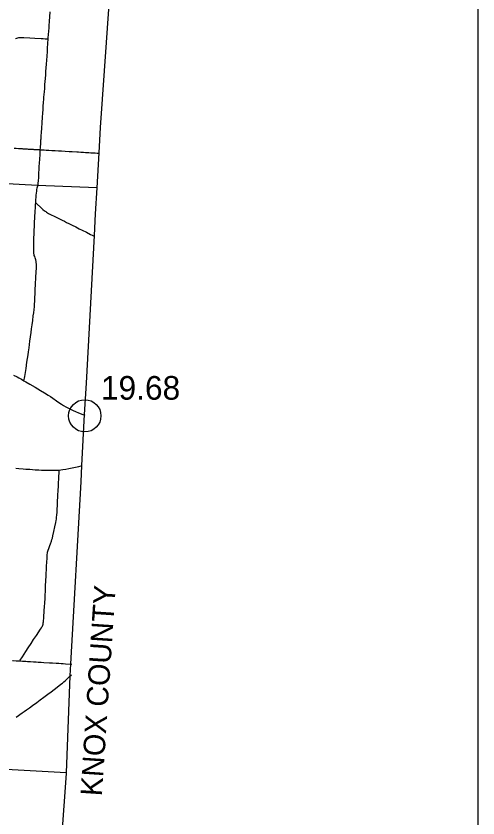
# Model space of a CAD drawing. Extents: x 1813937 to 1948437, y 826606 to 1022856.
# Drawn here: x 1926985 to 1948437, y 878544 to 915824 of the extents above; entities that cross this region are included whole.
import ezdxf

# ---------------------------------------------------------------- set-up
doc = ezdxf.new("R2010")
doc.units = 0
for name, color, linetype in [('Default', 7, 'Continuous'), ('GM_X_Adjacent_County_Text', 7, 'Continuous'), ('GM_X_County', 7, 'Continuous'), ('GM_X_County_Road', 7, 'Continuous'), ('GM_X_State_Route', 7, 'Continuous'), ('GM_X_Township', 7, 'Continuous'), ('GM_X_Township_Road', 7, 'Continuous'), ('SC_Scratch1', 7, 'Continuous')]:
    doc.layers.add(name, color=color, linetype=linetype)

msp = doc.modelspace()

# ---------------------------------------------------------------- linework, layer by layer
at = {"layer": 'Default'}
msp.add_circle((1930177, 897239), 750, dxfattribs=at)
at = {"layer": 'GM_X_County'}
msp.add_lwpolyline([(1931473, 919044), (1931168, 914595), (1930891, 910644), (1930824, 909461), (1930733, 907844), (1930665, 906634), (1930611, 905616), (1930247, 898751), (1930144, 897297), (1930019, 894924), (1929994, 894165), (1929509, 885709), (1929483, 885147), (1929313, 880637), (1929312, 880613), (1928987, 876105)], dxfattribs=at)
at = {"layer": 'GM_X_County_Road'}
for points in [[(1926898, 909680), (1926996, 909675), (1927094, 909669), (1927223, 909662), (1927270, 909659), (1927305, 909657), (1927346, 909654), (1927391, 909652), (1927420, 909650), (1927464, 909647), (1927502, 909645), (1927550, 909642), (1927602, 909639), (1927632, 909637), (1927662, 909636), (1927708, 909633), (1927749, 909630), (1927785, 909628), (1927815, 909626), (1927979, 909618), (1928077, 909613), (1928111, 909611)], [(1928111, 909611), (1928158, 909609), (1928289, 909601), (1928387, 909594), (1928502, 909587), (1928649, 909580), (1928714, 909577), (1928796, 909572), (1928960, 909561), (1929091, 909553), (1929270, 909541), (1929447, 909531), (1929512, 909527), (1929594, 909522), (1929806, 909511), (1929887, 909506), (1929986, 909499), (1930116, 909490), (1930214, 909485), (1930361, 909477), (1930459, 909472), (1930590, 909465), (1930655, 909461), (1930754, 909453), (1930800, 909450), (1930838, 909448)], [(1926968, 894804), (1927115, 894792), (1927311, 894776), (1927442, 894766), (1927622, 894754), (1927867, 894734), (1928047, 894722), (1928162, 894715), (1928244, 894711), (1928326, 894710), (1928457, 894710), (1928555, 894711), (1928834, 894712), (1928933, 894714), (1928990, 894718)], [(1928990, 894718), (1928998, 894718), (1929063, 894726), (1929161, 894741), (1929290, 894765), (1929435, 894792), (1929596, 894823), (1929902, 894884), (1930012, 894908), (1930062, 894919)], [(1926812, 885867), (1926846, 885865), (1926994, 885854), (1927157, 885843)], [(1927157, 885843), (1927288, 885835), (1927435, 885826), (1927517, 885821), (1927657, 885814), (1927789, 885807), (1927919, 885800), (1928009, 885794), (1928153, 885786), (1928270, 885778), (1928545, 885762), (1928678, 885753), (1928842, 885744), (1928973, 885736), (1929087, 885728), (1929169, 885722), (1929283, 885715), (1929581, 885699)], [(1926983, 883225), (1927102, 883312), (1927155, 883351), (1927261, 883427), (1927356, 883492), (1927477, 883576), (1927611, 883670), (1927745, 883766), (1927942, 883913), (1928101, 884029), (1928272, 884157), (1928468, 884304), (1928613, 884412), (1928888, 884619), (1929072, 884757), (1929136, 884809), (1929211, 884873), (1929259, 884917), (1929400, 885055), (1929471, 885123), (1929555, 885194)]]:
    msp.add_lwpolyline(points, dxfattribs=at)
at = {"layer": 'GM_X_State_Route'}
msp.add_lwpolyline([(1926872, 899129), (1927033, 899047), (1927120, 899000), (1927234, 898936), (1927353, 898868), (1927444, 898813), (1927628, 898706), (1927869, 898566), (1927996, 898492), (1928123, 898417), (1928306, 898308), (1928474, 898206), (1928585, 898135), (1928693, 898062), (1928866, 897938), (1928974, 897862), (1929097, 897780), (1929194, 897720), (1929294, 897662), (1929395, 897607), (1929511, 897547), (1929630, 897491), (1929750, 897438), (1929780, 897425), (1929856, 897393), (1930039, 897321), (1930185, 897266)], dxfattribs=at)
at = {"layer": 'GM_X_Township'}
for points in [[(1930733, 907844), (1927982, 907939), (1924001, 908161), (1918864, 908449), (1913461, 908761), (1908659, 909041), (1907683, 909106), (1907386, 909123), (1907188, 909134), (1903661, 909327), (1903767, 911000), (1903873, 912675), (1904049, 915466), (1901695, 915145), (1901024, 915054), (1891076, 913698), (1890078, 913562)], [(1929313, 880637), (1926519, 880798), (1923978, 880945), (1923826, 880954), (1918127, 881283), (1915079, 881414), (1912418, 881561), (1907482, 881867), (1902065, 882212), (1902276, 885593), (1902366, 887154), (1902378, 887248), (1902624, 890798), (1902935, 895772), (1903241, 901246), (1903453, 905734), (1903500, 906547), (1903661, 909327)]]:
    msp.add_lwpolyline(points, dxfattribs=at)
at = {"layer": 'GM_X_Township_Road'}
for points in [[(1928479, 914761), (1928482, 914800), (1928495, 914980), (1928504, 915111), (1928516, 915291), (1928524, 915389), (1928538, 915569), (1928569, 916027)], [(1926956, 914779), (1927019, 914798), (1927067, 914812), (1927115, 914822), (1927163, 914829), (1927212, 914833), (1927262, 914834), (1927344, 914831), (1927622, 914815), (1927851, 914798), (1928146, 914781), (1928244, 914775), (1928342, 914768), (1928391, 914765), (1928423, 914764), (1928453, 914762), (1928479, 914761)], [(1928111, 909611), (1928118, 909691), (1928122, 909730), (1928125, 909770), (1928129, 909854), (1928134, 909920), (1928137, 909984), (1928141, 910028), (1928143, 910062), (1928145, 910109), (1928147, 910131), (1928149, 910157), (1928150, 910172), (1928154, 910236), (1928167, 910433), (1928179, 910597), (1928196, 910875), (1928212, 911104), (1928224, 911317), (1928237, 911464), (1928249, 911627), (1928263, 911807), (1928274, 911954), (1928282, 912053), (1928301, 912298), (1928314, 912461), (1928327, 912641), (1928339, 912788), (1928361, 913082), (1928374, 913246), (1928384, 913410), (1928396, 913590), (1928423, 913966), (1928438, 914178), (1928449, 914326), (1928464, 914555), (1928479, 914761)], [(1928004, 907983), (1928019, 908068), (1928026, 908149), (1928035, 908336), (1928044, 908498), (1928056, 908728), (1928063, 908842), (1928072, 908973), (1928085, 909187), (1928097, 909368), (1928105, 909502), (1928110, 909585), (1928111, 909611)], [(1927900, 907146), (1927910, 907290), (1927916, 907388), (1927926, 907502), (1927945, 907681), (1927954, 907747), (1927972, 907844), (1928004, 907983)], [(1927353, 898868), (1927378, 898982), (1927392, 899062), (1927447, 899435), (1927491, 899727), (1927541, 900067), (1927562, 900213), (1927588, 900392), (1927632, 900717), (1927658, 900912), (1927684, 901107), (1927708, 901286), (1927730, 901465), (1927758, 901676), (1927785, 901887), (1927805, 902034), (1927822, 902180), (1927834, 902311), (1927841, 902409), (1927850, 902589), (1927858, 902753), (1927866, 902900), (1927875, 903129), (1927886, 903330), (1927892, 903462), (1927897, 903554), (1927905, 903684), (1927919, 903911), (1927923, 903977), (1927927, 904063), (1927931, 904173), (1927934, 904233), (1927933, 904295), (1927926, 904370), (1927917, 904420), (1927904, 904484), (1927874, 904577), (1927850, 904640), (1927830, 904694), (1927820, 904731), (1927815, 904770), (1927812, 904796), (1927810, 904822), (1927808, 904861), (1927807, 904907), (1927806, 904949), (1927807, 905113), (1927812, 905424), (1927815, 905539), (1927819, 905654), (1927827, 905857), (1927837, 906063), (1927847, 906227), (1927861, 906456), (1927877, 906751), (1927885, 906915), (1927895, 907078), (1927900, 907146)], [(1927900, 907146), (1927935, 907116), (1927972, 907084), (1928126, 906937), (1928235, 906837), (1928309, 906772), (1928360, 906731), (1928400, 906703), (1928442, 906677), (1928499, 906645), (1928616, 906586), (1928748, 906520), (1928820, 906482), (1928908, 906439), (1928996, 906395), (1929099, 906347), (1929128, 906333), (1929231, 906284), (1929333, 906233), (1929435, 906181), (1929597, 906102), (1929758, 906020), (1929919, 905939), (1930051, 905874), (1930255, 905770), (1930445, 905672), (1930519, 905637), (1930579, 905612), (1930620, 905598)], [(1927157, 885843), (1927183, 885884), (1927277, 886038), (1927357, 886162), (1927438, 886285), (1927545, 886450), (1927681, 886656), (1927799, 886833), (1927927, 887024), (1928126, 887325), (1928161, 887381), (1928184, 887423), (1928206, 887468), (1928223, 887514), (1928237, 887561), (1928248, 887609), (1928255, 887657), (1928263, 887723), (1928271, 887821), (1928280, 887968), (1928288, 888083), (1928295, 888197), (1928304, 888344), (1928319, 888557), (1928330, 888737), (1928341, 888950), (1928346, 889048), (1928353, 889212), (1928359, 889327), (1928371, 889589), (1928381, 889786), (1928387, 889933), (1928393, 890064), (1928398, 890146), (1928404, 890293), (1928408, 890392), (1928427, 890670), (1928434, 890785), (1928441, 890850), (1928449, 890898), (1928460, 890946), (1928474, 890993), (1928501, 891071), (1928554, 891209), (1928583, 891285), (1928629, 891408), (1928654, 891486), (1928672, 891549), (1928699, 891661), (1928746, 891869), (1928792, 892077), (1928836, 892286), (1928851, 892366), (1928860, 892431), (1928870, 892529), (1928877, 892627), (1928887, 892758), (1928894, 892905), (1928902, 893069), (1928907, 893151), (1928913, 893298), (1928920, 893446), (1928930, 893593), (1928937, 893724), (1928952, 894019), (1928960, 894166), (1928965, 894264), (1928971, 894346), (1928974, 894411), (1928985, 894590), (1928988, 894655), (1928989, 894672), (1928990, 894718)]]:
    msp.add_lwpolyline(points, dxfattribs=at)
at = {"layer": 'SC_Scratch1'}
msp.add_lwpolyline([(1813937, 826606), (1813937, 1022856), (1948437, 1022856), (1948437, 826606)], close=True, dxfattribs=at)

# ---------------------------------------------------------------- texts
at = {"layer": 'Default'}
msp.add_text('19.68', height=1100, dxfattribs=at).set_placement((1930927, 897989))
at = {"layer": 'GM_X_Adjacent_County_Text'}
msp.add_text('KNOX COUNTY', height=1000, rotation=86.2231, dxfattribs=at).set_placement((1930970, 879537))

doc.saveas('drawing.dxf')
